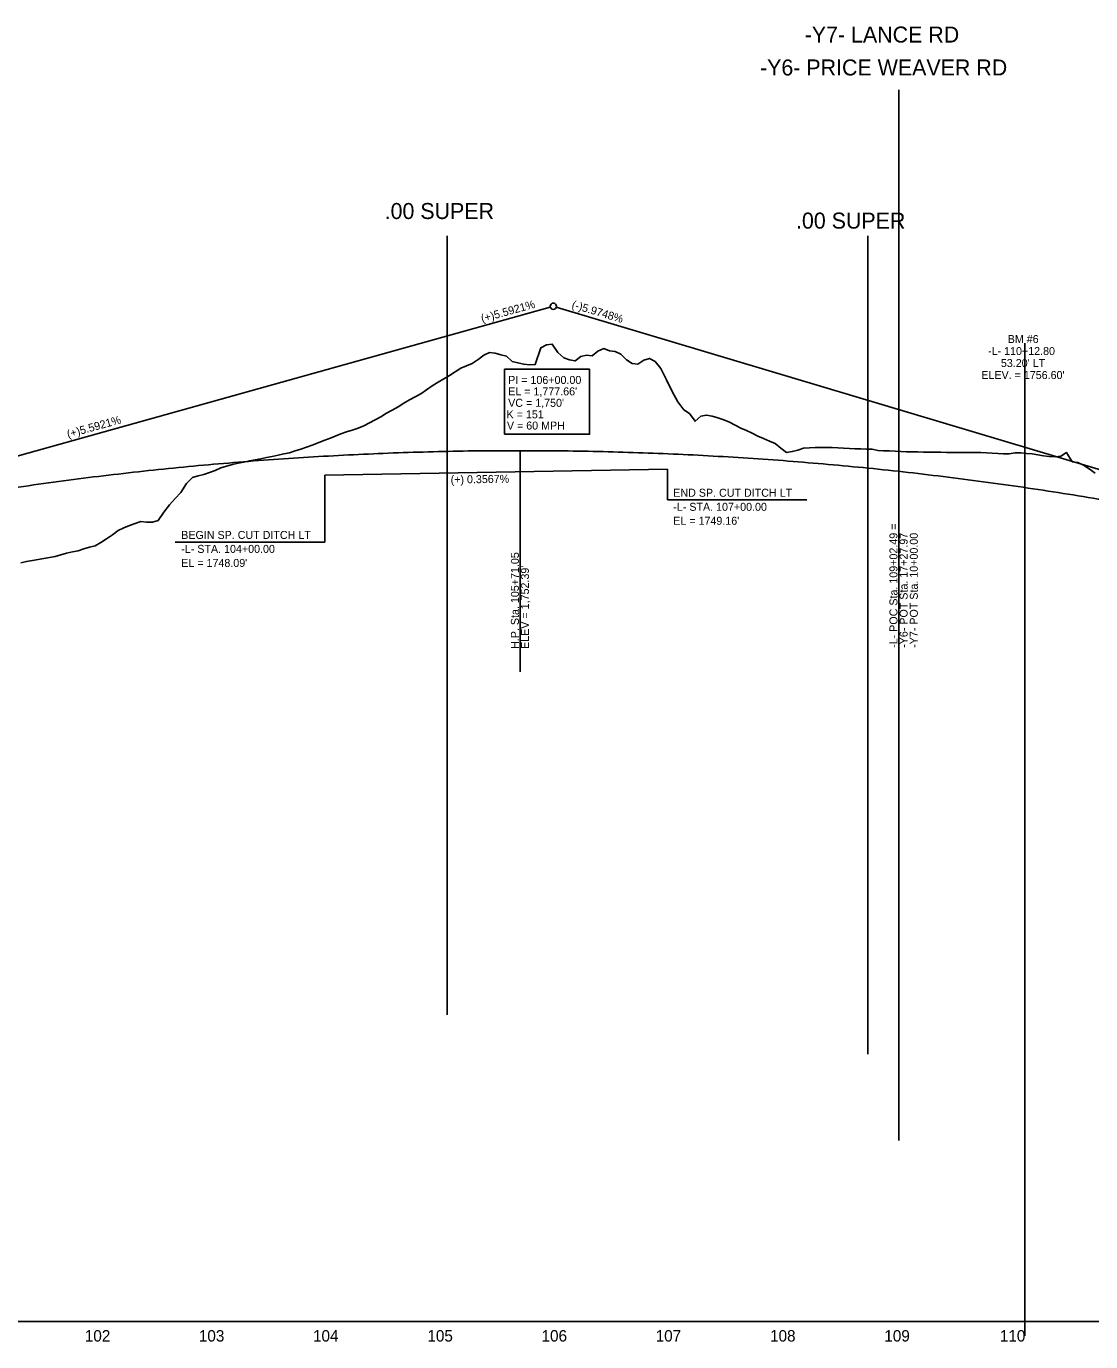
# Model space of a CAD drawing. Extents: x 498575 to 532350, y 405181 to 484585.
# Drawn here: x 514958 to 515889, y 483216 to 484367 of the extents above; entities that cross this region are included whole.
import ezdxf

# ---------------------------------------------------------------- set-up
doc = ezdxf.new("R2010")
doc.units = 0
for name, color, linetype in [('Exist Profile Cell', 7, 'Continuous'), ('Exist Vertical Profile Ground Line', 7, 'Continuous'), ('Exist Vertical Profile Horizontal Axis Label Major', 7, 'Continuous'), ('Prop Grid Mask', 7, 'Continuous'), ('Prop PFL Text', 7, 'Continuous'), ('Prop Vertical Profile Curve Label', 7, 'Continuous'), ('Prop Vertical Profile Ditch Grade Left', 7, 'Continuous'), ('Prop Vertical Profile Ditch Grade Left Label', 7, 'Continuous'), ('Prop Vertical Profile Grade', 7, 'Continuous'), ('Prop Vertical Profile Grade Label', 7, 'Continuous'), ('Prop Vertical Profile Strip Grade', 7, 'Continuous'), ('Prop VPI Label', 7, 'Continuous'), ('Scratch_Level_0', 7, 'Continuous'), ('Scratch_Level_2', 7, 'Continuous'), ('Scratch_Level_4', 7, 'Continuous')]:
    doc.layers.add(name, color=color, linetype=linetype)

msp = doc.modelspace()

# ---------------------------------------------------------------- linework, layer by layer
at = {"layer": 'Exist Profile Cell'}
msp.add_line((505856.7, 483233.7), (526056.7, 483233.7), dxfattribs=at)
at = {"layer": 'Exist Vertical Profile Ground Line'}
for points in [[(515313.2, 484052.3), (515318.2, 484055.6), (515323.2, 484058.5), (515328.2, 484061.5), (515333.2, 484064.6), (515338.2, 484067.7), (515343.2, 484069.8), (515348.2, 484071.9), (515353.2, 484075.3), (515358.2, 484079.3), (515363.2, 484081.5), (515368.2, 484081), (515373.2, 484079.5), (515378.2, 484078.3), (515383.2, 484073.6), (515388.2, 484072.6), (515393.2, 484071.3), (515398.2, 484070.8), (515403.2, 484070.9), (515408.2, 484085.6), (515413.2, 484088.2), (515418.2, 484088.7), (515423.2, 484081.6), (515428.2, 484076.8), (515433.2, 484075.2), (515438.2, 484074.1), (515443.2, 484078), (515448.2, 484079.3), (515453.2, 484078.7), (515458.2, 484082.6), (515463.2, 484085), (515468.2, 484082.9), (515473.2, 484082.4), (515478.2, 484080.1), (515483.2, 484075), (515488.2, 484071.9), (515493.2, 484071.3), (515498.2, 484074.8), (515503.2, 484076.3), (515508.2, 484073.6), (515513.2, 484067.6), (515518.2, 484057.7), (515523.2, 484047.3), (515528.2, 484038.3), (515533.2, 484031.4), (515538.2, 484028.1), (515543.2, 484021.4), (515548.2, 484025.7), (515553.2, 484026.7), (515558.2, 484025.7), (515563.2, 484024.4), (515568.2, 484022.7), (515573.2, 484020.5), (515578.2, 484017.8), (515583.2, 484015.3), (515588.2, 484013.3), (515593.2, 484010.8), (515598.2, 484008.3), (515603.2, 484006.2), (515608.2, 484004), (515613.2, 484001.8), (515618.2, 483997.8), (515623.2, 483994.1), (515628.2, 483994.8), (515633.2, 483996), (515638.2, 483997.7), (515643.2, 483998.1), (515648.2, 483998.5), (515653.2, 483998.5), (515658.2, 483998.4), (515663.2, 483998.4), (515668.2, 483998.2), (515673.2, 483997.9), (515678.2, 483997.5), (515683.2, 483997.2), (515688.2, 483997.1), (515693.2, 483997), (515698.2, 483996.8), (515703.2, 483995.9), (515708.2, 483995.6), (515713.2, 483995.4), (515718.2, 483995.1), (515723.2, 483994.8), (515728.2, 483994.7), (515733.2, 483994.6), (515738.2, 483994.5), (515743.2, 483994.4), (515748.2, 483994.4), (515753.2, 483994.3), (515758.2, 483994.2), (515763.2, 483994.1), (515768.2, 483993.9), (515773.2, 483994), (515778.2, 483994.1), (515783.2, 483993.9), (515788.2, 483994.1), (515793.2, 483994), (515798.2, 483993.7), (515803.2, 483993.4), (515808.2, 483993.1), (515813.2, 483992.8)], [(514953.2, 483897.6), (514958.2, 483898.6), (514963.2, 483899.5), (514968.2, 483900.4), (514973.2, 483901.3), (514978.2, 483902.3), (514983.2, 483903.1), (514988.2, 483904.5), (514993.2, 483905.9), (514998.2, 483907), (515003.2, 483908), (515008.2, 483909.6), (515013.2, 483911.1), (515018.2, 483912.4), (515023.2, 483915.2), (515028.2, 483918.5), (515033.2, 483922), (515038.2, 483925.9), (515043.2, 483928.1), (515048.2, 483930.2), (515053.2, 483932), (515058.2, 483933.6), (515063.2, 483933), (515068.2, 483933), (515073.2, 483934.5), (515078.2, 483941.8), (515083.2, 483948.2), (515088.2, 483953.7), (515093.2, 483958.9), (515098.2, 483966.9), (515103.2, 483972.1), (515108.2, 483973.6), (515113.2, 483974.7), (515118.2, 483976.4), (515123.2, 483978.3), (515128.2, 483980.7), (515133.2, 483982.1), (515138.2, 483983.4), (515143.2, 483984.6), (515148.2, 483985.7), (515153.2, 483986.6), (515158.2, 483987.6), (515163.2, 483988.6), (515168.2, 483989.7), (515173.2, 483990.6), (515178.2, 483991.7), (515183.2, 483992.8), (515188.2, 483993.8), (515193.2, 483995.4), (515198.2, 483996.9), (515203.2, 483998.6), (515208.2, 484000.5), (515213.2, 484002.4), (515218.2, 484004.4), (515223.2, 484006.4), (515228.2, 484008.4), (515233.2, 484010.4), (515238.2, 484012.1), (515243.2, 484013.5), (515248.2, 484015.2), (515253.2, 484017.4), (515258.2, 484019.9), (515263.2, 484022.5), (515268.2, 484025.1), (515273.2, 484028.4), (515278.2, 484031.2), (515283.2, 484034.1), (515288.2, 484037.3), (515293.2, 484040.2), (515298.2, 484042.7), (515303.2, 484045.3), (515308.2, 484048.8), (515313.2, 484052.3)], [(515813.2, 483992.8), (515818.2, 483992.9), (515823.2, 483993.6), (515828.2, 483993.7), (515833.2, 483993.2), (515838.2, 483992.8), (515843.2, 483991.9), (515848.2, 483991), (515853.2, 483990.6), (515858.2, 483990.1), (515863.2, 483990.8), (515868.2, 483994.1), (515873.2, 483986), (515878.2, 483985.4), (515883.2, 483982.8), (515888.2, 483979.8), (515893.2, 483976)]]:
    msp.add_lwpolyline(points, dxfattribs=at)
at = {"layer": 'Prop Grid Mask'}
msp.add_lwpolyline([(515376.4, 484010), (515450.8, 484010), (515450.8, 484066.8), (515376.4, 484066.8)], close=True, dxfattribs=at)
at = {"layer": 'Prop Vertical Profile Ditch Grade Left'}
msp.add_lwpolyline([(515219.1, 483974.2), (515519.1, 483979.5), (515519.1, 483979.5)], dxfattribs=at)
at = {"layer": 'Prop Vertical Profile Ditch Grade Left Label'}
for p, q in [((515219.1, 483974.2), (515219.1, 483915.7)), ((515519.1, 483979.5), (515519.1, 483952.6)), ((515519.1, 483952.6), (515641.1, 483952.6)), ((515088.3, 483915.7), (515219.1, 483915.7))]:
    msp.add_line(p, q, dxfattribs=at)
at = {"layer": 'Prop Vertical Profile Grade'}
msp.add_spline([(514544.1, 483877.4), (514579.1, 483886.9), (514614.1, 483896.1), (514649.1, 483904.9), (514684.1, 483913.3), (514719.1, 483921.2), (514754.1, 483928.8), (514789.1, 483935.9), (514824.1, 483942.7), (514859.1, 483949), (514894.1, 483955), (514929.1, 483960.5), (514964.1, 483965.6), (514999.1, 483970.4), (515034.1, 483974.7), (515069.1, 483978.6), (515104.1, 483982.1), (515139.1, 483985.2), (515174.1, 483987.9), (515209.1, 483990.2), (515244.1, 483992.1), (515279.1, 483993.6), (515314.1, 483994.7), (515349.1, 483995.4), (515384.1, 483995.6), (515419.1, 483995.5), (515454.1, 483995), (515489.1, 483994), (515524.1, 483992.7), (515559.1, 483990.9), (515594.1, 483988.8), (515629.1, 483986.2), (515664.1, 483983.2), (515699.1, 483979.9), (515734.1, 483976.1), (515769.1, 483971.9), (515804.1, 483967.3), (515839.1, 483962.3), (515874.1, 483956.9), (515909.1, 483951.1), (515944.1, 483944.9), (515979.1, 483938.3), (516014.1, 483931.3), (516049.1, 483923.9), (516084.1, 483916.1), (516119.1, 483907.8), (516154.1, 483899.2), (516189.1, 483890.2), (516224.1, 483880.7), (516259.1, 483870.9), (516294.1, 483860.6)], degree=3, dxfattribs=at)
at = {"layer": 'Prop Vertical Profile Strip Grade'}
for p, q in [((515390.1, 483995.6), (515390.1, 483802.2)), ((515721.6, 483819.9), (515721.6, 483977.5))]:
    msp.add_line(p, q, dxfattribs=at)
at = {"layer": 'Prop VPI Label'}
for p, q in [((514544.1, 483877.4), (515416.4, 484121.3)), ((516294.1, 483860.6), (515421.7, 484121.2))]:
    msp.add_line(p, q, dxfattribs=at)
msp.add_circle((515419.1, 484122), 2.75, dxfattribs=at)
at = {"layer": 'Scratch_Level_0'}
msp.add_line((515831.9, 483221.2), (515831.9, 484089.8), dxfattribs=at)
at = {"layer": 'Scratch_Level_2'}
msp.add_line((515721.6, 484311.3), (515721.6, 483392.1), dxfattribs=at)
at = {"layer": 'Scratch_Level_4'}
for p, q in [((515326.2, 484183.7), (515326.2, 483502)), ((515694.3, 484183.7), (515694.3, 483467.6))]:
    msp.add_line(p, q, dxfattribs=at)

# ---------------------------------------------------------------- texts
at = {"layer": 'Exist Vertical Profile Horizontal Axis Label Major'}
for s, p in [('102', (515009.1, 483216.2)), ('102', (515009.1, 483216.2)), ('103', (515108.9, 483216.2)), ('103', (515108.9, 483216.2)), ('104', (515208.8, 483216.2)), ('104', (515208.8, 483216.2)), ('105', (515308.9, 483216.2)), ('105', (515308.9, 483216.2)), ('106', (515408.8, 483216.2)), ('106', (515408.8, 483216.2)), ('107', (515508.7, 483216.2)), ('107', (515508.7, 483216.2)), ('108', (515608.8, 483216.2)), ('108', (515608.8, 483216.2)), ('109', (515708.8, 483216.2)), ('109', (515708.8, 483216.2)), ('110', (515809.9, 483216.2)), ('110', (515809.9, 483216.2))]:
    msp.add_text(s, height=10, dxfattribs=at).set_placement(p)
at = {"layer": 'Prop PFL Text'}
for s, p in [('-L- 110+12.80', (515799.6, 484079.3)), ('BM #6', (515816.8, 484089.8)), ("53.20' LT", (515810.8, 484068.8)), ("ELEV. = 1756.60'", (515793.7, 484058.3))]:
    msp.add_text(s, height=7, dxfattribs=at).set_placement(p)
at = {"layer": 'Prop Vertical Profile Curve Label'}
for s, p in [("VC = 1,750'", (515379.6, 484034)), ('K = 151', (515378.2, 484023.9)), ('V = 60 MPH ', (515378.5, 484014.1))]:
    msp.add_text(s, height=7, dxfattribs=at).set_placement(p)
at = {"layer": 'Prop Vertical Profile Ditch Grade Left Label'}
for s, rotation, p in [('(+) 0.3567%', 0.7148, (515329.3, 483966.9)), ('END SP. CUT DITCH LT', 360, (515524.1, 483955.3)), ('-L- STA. 107+00.00', 360, (515524.1, 483943)), ("EL = 1749.16'", 360, (515524.1, 483930.8)), ('BEGIN SP. CUT DITCH LT', 360, (515093.5, 483918.4)), ('-L- STA. 104+00.00', 360, (515093.5, 483906.2)), ("EL = 1748.09'", 360, (515093.5, 483893.9))]:
    msp.add_text(s, height=7, rotation=rotation, dxfattribs=at).set_placement(p)
at = {"layer": 'Prop Vertical Profile Grade Label'}
for s, rotation, p in [('(+)5.5921%', 15.6213, (515356.9, 484107.7)), ('(-)5.9748%', 343.3671, (515434.7, 484120.5)), ('(+)5.5921%', 15.6213, (514994.5, 484006.6))]:
    msp.add_text(s, height=7, rotation=rotation, dxfattribs=at).set_placement(p)
at = {"layer": 'Prop Vertical Profile Strip Grade'}
for s, p in [('-L- POC Sta. 109+02.49 = ', (515720.3, 483823.1)), ('-Y6- POT Sta. 17+27.97', (515729.2, 483823.1)), ('-Y7- POT Sta. 10+00.00', (515738.1, 483823.1)), ('H.P. Sta. 105+71.05', (515389, 483822.2)), ("ELEV = 1,752.39'", (515397.8, 483822.2))]:
    msp.add_text(s, height=7, rotation=90, dxfattribs=at).set_placement(p)
at = {"layer": 'Prop VPI Label'}
for s, p in [('PI = 106+00.00', (515379.6, 484054)), ("EL = 1,777.66'", (515379.6, 484044))]:
    msp.add_text(s, height=7, dxfattribs=at).set_placement(p)
at = {"layer": 'Scratch_Level_2'}
for s, p in [('-Y7- LANCE RD', (515639.1, 484352.7)), ('-Y6- PRICE WEAVER RD', (515600, 484323.9))]:
    msp.add_text(s, height=14, dxfattribs=at).set_placement(p)
at = {"layer": 'Scratch_Level_4'}
for p in [(515271.5, 484198.3), (515631.5, 484189.9)]:
    msp.add_text('.00 SUPER', height=14, dxfattribs=at).set_placement(p)

doc.saveas('drawing.dxf')
